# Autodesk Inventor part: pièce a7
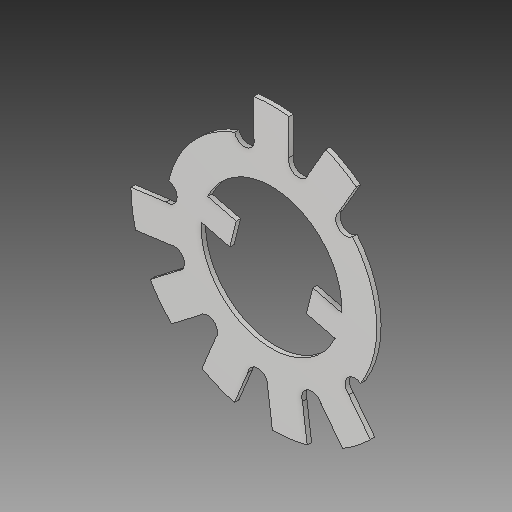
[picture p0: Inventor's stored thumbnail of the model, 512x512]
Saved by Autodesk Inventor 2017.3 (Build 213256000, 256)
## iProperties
Created: 2007-12
Part Number: pièce a7
Material: Générique
Document SubType Name: Modeling
Designer: ficho
Density: 1 g/cm^3
Appearance: Par défaut
Author: ficho
Sending System: SolidWorks 2009
Last Author: christophe
Last Saved: 2011-02-10
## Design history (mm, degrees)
extrude "Extrusion1"
node "Solide1"
